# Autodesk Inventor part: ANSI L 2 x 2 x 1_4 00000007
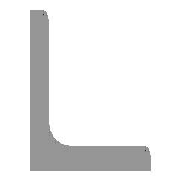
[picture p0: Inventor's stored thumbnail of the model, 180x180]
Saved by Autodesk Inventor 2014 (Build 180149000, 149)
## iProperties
_FrameMemberDoc: Frame Member File
_Version: 15.0.0
_CCFamilyMember: 11
_CCFamilyDisplayName: ANSI L (Equal angles) - Angle Steel
Created: 2007-02
Part Number: ANSI L 2 x 2 x 1_4 00000007
Material: Steel, Mild
Document SubType Name: Modeling
Standard: AISC
Designer: Autodesk, Inc.
Size Designation: L 2 x 2 x 1/4
Stock Number: L 2 x 2 x 1/4
Density: 7.86 g/cm^3
Description: Angle Steel
Standards Organization: ANSI
Language: en-US
Categories: <MemberInstance><Categories><Category DisplayName="Structural Shapes" InternalName="089c4875-fa83-4c05-b084-43b9cc11f5ed" Mnemonic="GRDR"><CategoryParameter Dis
Mass: 3370.02 g
Surface Area: 1403.81 cm^2
Volume: 428.755 cm^3
Appearance: Steel
IsCustomPart: 1
G_L: 28.000 in
G_W: 2.000 in
G_H: 2.000 in
+9DA12A09-7987-4B55-8365-5F2745A41632+CUTDETAIL1: Notch
+8877337F-ED1B-4323-9579-95701C6C6C0A+CUTDETAIL2: Notch
Author: Autodesk, Inc.
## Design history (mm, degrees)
node "Start plane"
node "End plane"
sketch "Sketch"
  geometry: L1 (50.8, 0)-(0, 0); L2 (0, 0)-(0, 50.8); L3 (0, 50.8)-(3.302, 50.8); L4 (6.35, 47.752)-(6.35, 12.7); L5 (12.7, 6.35)-(47.752, 6.35); L6 (50.8, 3.302)-(50.8, 0); L7 (0, -11.041)-(0, 31.538); L8 (-11.041, 0)-(31.538, 0); L9 (0, 63.926)-(0, -23.536) reference; L10 (-23.536, 0)-(63.926, 0) reference; A1 r 6.35 centre (12.7, 12.7) between (6.35, 12.7) and (12.7, 6.35); A2 r 3.048 centre (3.302, 47.752) between (6.35, 47.752) and (3.302, 50.8); A3 r 3.048 centre (47.752, 3.302) between (50.8, 3.302) and (47.752, 6.35); 3 further points
  constraints: 16 end point, 6 point on circle, 6 point on line, 6 tangent, 4 parallel, 3 centre point, 2 collinear, 1 equal radius, 1 horizontal, 1 perpendicular
  dimensions: "d0" = 50.8 distance between parallel lines of L6 L2 (= G_H); "d1" = 50.8 distance between parallel lines of L3 L1 (= G_H); "d2" = 6.35 distance between parallel lines of L2 L4 (= G_T); "d3" = 6.35 distance between parallel lines of L1 L5 (= G_T); "d10" = 0 distance between parallel lines of L7 L2 (computed from ex); "d11" = 0 distance between parallel lines of L8 L1 (computed from d10); "d14" = 6.35 radius of A1 (= G_IR); "d15" = 3.048 radius of A2 (= G_ER)
extrude "Body" new body sketch "Sketch" stored distance "d4" = 711.2 (= G_L); taper "d5" = 0 deg
node "Driven Length"
  sketch "Sketch5"
    geometry: L1 (0, 0)-(10, 0) reference
    constraints: 2 end point, 1 horizontal
  workplane "Work Plane7"
  sketch "Sketch6"
    geometry: L1 (-2, 0)-(12, 0) reference; L2 (-2, 711.2)-(12, 711.2) reference
    dimensions: "d21" = 711.2 distance between parallel lines of L1 L2 (derived)
workplane "Work Plane3"
workplane "Work Plane4"
workplane "Work Plane5"
workplane "Work Plane6"
workplane "Work Plane8"
workplane "Work Plane9"
body "Solid1"
sketch "Sketch_1"
  geometry: L1 (50.8, 0)-(0, 0); L2 (0, 0)-(0, 50.8); L3 (0, 50.8)-(3.302, 50.8); L4 (6.35, 47.752)-(6.35, 12.7); L5 (12.7, 6.35)-(47.752, 6.35); L6 (50.8, 3.302)-(50.8, 0); A1 r 3.048 centre (3.302, 47.752) between (6.35, 47.752) and (3.302, 50.8); A2 r 6.35 centre (12.7, 12.7) between (6.35, 12.7) and (12.7, 6.35); A3 r 3.048 centre (47.752, 3.302) between (50.8, 3.302) and (47.752, 6.35)
  constraints: 12 end point, 6 point on circle, 3 centre point
extrude "Extrusion2" cut sketch "Sketch_1" stored distance "d22" = 3.302; taper "d23" = 0 deg
sketch "Sketch_2"
  geometry: L1 (50.8, 0)-(0, 0); L2 (0, 0)-(0, 50.8); L3 (0, 50.8)-(3.302, 50.8); L4 (6.35, 47.752)-(6.35, 12.7); L5 (12.7, 6.35)-(47.752, 6.35); L6 (50.8, 3.302)-(50.8, 0); A1 r 3.048 centre (3.302, 47.752) between (6.35, 47.752) and (3.302, 50.8); A2 r 6.35 centre (12.7, 12.7) between (6.35, 12.7) and (12.7, 6.35); A3 r 3.048 centre (47.752, 3.302) between (50.8, 3.302) and (47.752, 6.35)
  constraints: 12 end point, 6 point on circle, 3 centre point
extrude "Extrusion3" cut sketch "Sketch_2" stored distance "d24" = 3.302; taper "d25" = 0 deg
other parameters: "G_H" = 50.8 [user parameter; used in 2 equation terms], "G_T" = 6.35 [user parameter; used in 2 equation terms], "G_ER" = 3.048 [user parameter; used in 1 equation term], "G_IR" = 6.35 [user parameter; used in 1 equation term], "G_L" = 711.2 (= d21) [user parameter; used in 1 equation term], "ex" = 0 [user parameter; used in 1 equation term], "G_OFFSET_START" = 0 [user parameter; used in 1 equation term], "G_OFFSET_END" = 0 [user parameter; used in 1 equation term], "d12" = 0 (computed from G_OFFSET_START), "d13" = 711.2 (= G_OFFSET_END + B_L), "B_L" = 711.2 [user parameter; used in 1 equation term], "d20" = 90 deg
